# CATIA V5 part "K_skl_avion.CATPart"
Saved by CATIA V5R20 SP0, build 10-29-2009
Part number: skl_avion
Publications: "longueur axe pivot", "liaison avion 3/10", "liaison avion 24/28", "Plan.-100", "Droite.1", "Droite.2", "Droite.3"
Bounding box of the stored display mesh (mm): x -250 to -100, y -720 to 340, z 0 to 0
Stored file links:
  G:\Khaled_CFAO_2011\SIL\SIL_GR2\mdardier\Khaled\CAD_ThinkMOTION\K_skl_avion.CATPart
  G:\Khaled_CFAO_2011\SIL\SIL_GR2\mdardier\Khaled\CAD_ThinkMOTION\K_skl_ass_tandem.CATProduct
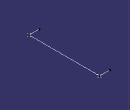
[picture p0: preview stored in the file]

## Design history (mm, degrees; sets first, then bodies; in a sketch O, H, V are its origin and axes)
External parameters (linked from other documents)
  `External.longueur axe pivot` = 150 mm
Set1
  Point1 "liaison avion 3/10": linked copy from another document
  Point2 "liaison avion 24/28": linked copy from another document
  Plane1 "Plan.-100": linked copy from another document
Set2
  Line1: type PtPt, FirstPoint Point1, SecondPoint Point2
  Line2: type Normal, RefPoint Point1, RefSkin Plane1, Start 0, End 150 {= `External.longueur axe pivot`}
  Line3: type Normal, RefPoint Point2, RefSkin Plane1, Start 0, End 150 {= `External.longueur axe pivot`}
Body1 (main body)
